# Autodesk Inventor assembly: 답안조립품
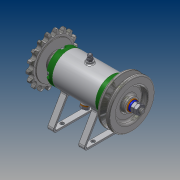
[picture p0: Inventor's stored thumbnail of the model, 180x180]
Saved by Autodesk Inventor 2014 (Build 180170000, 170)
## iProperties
Created: 2016-03
Part Number: 답안조립품
Document SubType Name: Assembly
Designer: SEC
Author: SEC
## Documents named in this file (16)
- C:\Documents and Settings\SEC\바탕 화면\460307V1019\답안조립품.iam
- C:\Documents and Settings\SEC\바탕 화면\460307V1019\본체.ipt
- C:\Documents and Settings\SEC\바탕 화면\460307V1019\너트 M 8.ipt
- C:\Documents and Settings\SEC\바탕 화면\460307V1019\니플 M 6 x 0.75.ipt
- C:\Documents and Settings\SEC\바탕 화면\460307V1019\베어링 15 x 32 x 9.ipt
- C:\Documents and Settings\SEC\바탕 화면\460307V1019\볼트 M4 x 12.ipt
- C:\Documents and Settings\SEC\바탕 화면\460307V1019\볼트 M 6 x 8.ipt
- C:\Documents and Settings\SEC\바탕 화면\460307V1019\스프로킷.ipt
- C:\Documents and Settings\SEC\바탕 화면\460307V1019\스프링와셔 8.ipt
- C:\Documents and Settings\SEC\바탕 화면\460307V1019\오일 실 15 25 7.ipt
- C:\Documents and Settings\SEC\바탕 화면\460307V1019\와셔 6x11.5.ipt
- C:\Documents and Settings\SEC\바탕 화면\460307V1019\와셔 8x17.ipt
- C:\Documents and Settings\SEC\바탕 화면\460307V1019\축.ipt
- C:\Documents and Settings\SEC\바탕 화면\460307V1019\커버.ipt
- C:\Documents and Settings\SEC\바탕 화면\460307V1019\키 3 x 3 x 12.ipt
- C:\Documents and Settings\SEC\바탕 화면\460307V1019\V벨트풀리.ipt
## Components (11 placed, 3 different names)
1. KS B 2023 6002 - 15 x 32 x 9:1
2. V벨트풀리:1 — 각도:8
3. KS B 2023 6002 - 15 x 32 x 9:2
4. ISO 4762 M4 x 12:2 — 각도:5
5. ISO 4762 M4 x 12:3
6. ISO 4762 M4 x 12:4
7. ISO 4762 M4 x 12:5
8. ISO 4762 M4 x 12:1 — 각도:6
9. ISO 4762 M4 x 12:6
10. ISO 4762 M4 x 12:7
11. ISO 4762 M4 x 12:8
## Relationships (3: Angle 3)
- 각도:5 [Angle]: ISO 4762 M4 x 12:2
- 각도:6 [Angle]: ISO 4762 M4 x 12:1
- 각도:8 [Angle]: V벨트풀리:1
